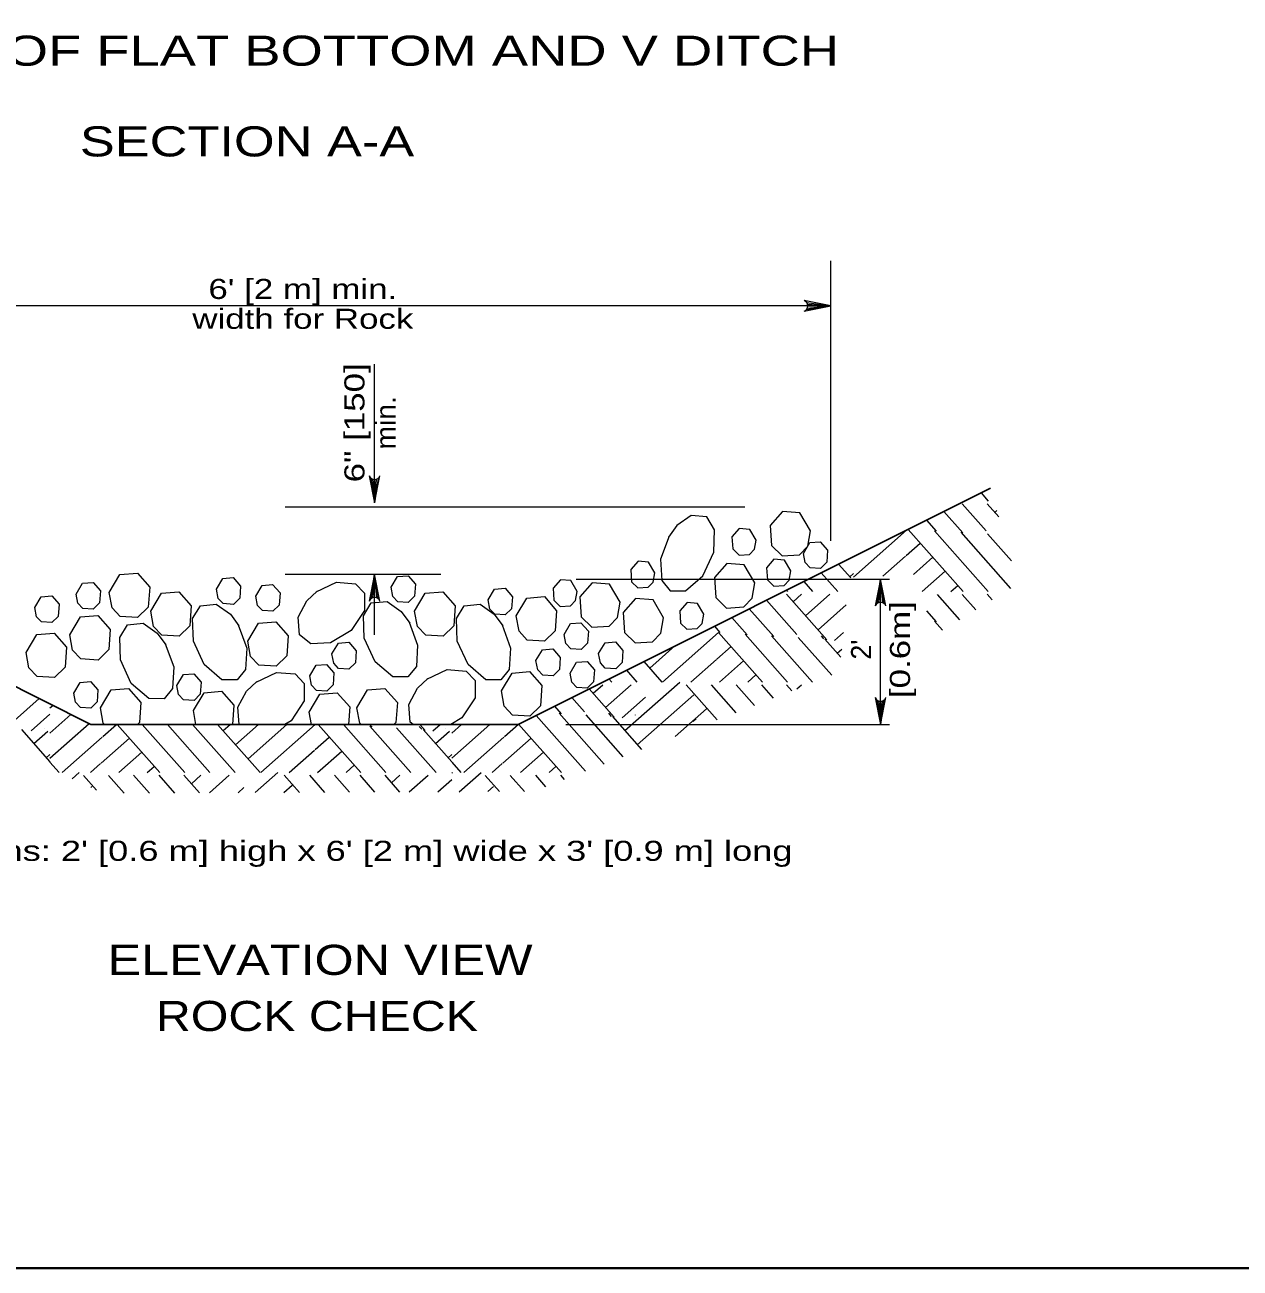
# Model space of a CAD drawing. Extents: x 1083.1 to 1117.1, y 672.5 to 716.5.
# Drawn here: x 1090.8 to 1100.48, y 695.01 to 704.92 of the extents above; entities that cross this region are included whole.
import ezdxf
from ezdxf.enums import TextEntityAlignment as Align

# ---------------------------------------------------------------- set-up
doc = ezdxf.new("R2010")
doc.units = 0
doc.header["$LTSCALE"] = 0.062
doc.layers.add('1', color=7, linetype='Continuous', lineweight=13)

msp = doc.modelspace()

# ---------------------------------------------------------------- linework, layer by layer
at = {"layer": '1'}
for p, q in [((1097.22183, 700.80767), (1097.22183, 703.03942)), ((1097.02833, 702.7075), (1097.22183, 702.68042)), ((1097.22183, 702.68042), (1088.68708, 702.68042)), ((1097.026, 702.6505), (1097.22183, 702.68042)), ((1097.03342, 702.663), (1097.22183, 702.68042)), ((1097.03483, 702.69408), (1097.22183, 702.68042)), ((1097.03683, 702.68042), (1097.22183, 702.68042)), ((1097.04342, 702.68042), (1097.21917, 702.68042)), ((1093.58383, 701.11083), (1093.58383, 702.21525)), ((1093.55392, 701.30667), (1093.58383, 701.11083)), ((1093.56642, 701.29925), (1093.58383, 701.11083)), ((1093.61092, 701.30433), (1093.58383, 701.11083)), ((1093.5975, 701.29783), (1093.58383, 701.11083)), ((1093.58383, 701.29583), (1093.58383, 701.11083)), ((1093.58383, 701.28925), (1093.58383, 701.1135)), ((1098.41883, 701.18875), (1098.47633, 701.12375)), ((1092.8715, 701.07808), (1096.53592, 701.07808)), ((1098.12233, 701.0405), (1098.27333, 700.86983)), ((1098.26875, 701.10192), (1098.45992, 700.8855)), ((1098.46875, 701.102), (1098.56025, 700.9985)), ((1098.52842, 701.03425), (1098.54558, 701.04942)), ((1097.98342, 700.97108), (1098.06125, 700.88292)), ((1097.40125, 700.51742), (1097.82458, 700.89158)), ((1097.83758, 700.89808), (1098.27625, 700.40225)), ((1097.84483, 700.90175), (1097.84633, 700.9)), ((1098.04667, 700.888), (1098.47633, 700.40225)), ((1098.25825, 700.875), (1098.65442, 700.42758)), ((1098.47058, 700.86208), (1098.66142, 700.64633)), ((1097.82217, 700.68933), (1097.93442, 700.78867)), ((1097.63658, 700.52542), (1097.81758, 700.68558)), ((1097.87908, 700.53925), (1098.03408, 700.67633)), ((1092.8715, 700.54083), (1094.1115, 700.54083)), ((1093.55675, 700.34733), (1093.58383, 700.54083)), ((1093.57017, 700.35383), (1093.58383, 700.54083)), ((1093.58383, 700.05758), (1093.58383, 700.54083)), ((1093.58383, 700.35583), (1093.58383, 700.54083)), ((1093.60125, 700.35242), (1093.58383, 700.54083)), ((1093.61375, 700.345), (1093.58383, 700.54083)), ((1093.58383, 700.36242), (1093.58383, 700.53817)), ((1097.14458, 700.55167), (1097.27675, 700.40225)), ((1097.28342, 700.621), (1097.38092, 700.51083)), ((1097.37192, 700.521), (1097.40125, 700.54692)), ((1097.9505, 700.40225), (1098.13342, 700.56408)), ((1095.19067, 700.50125), (1097.6885, 700.50125)), ((1097.00542, 700.482), (1097.076, 700.40225)), ((1097.59025, 700.30775), (1097.61733, 700.50125)), ((1097.60367, 700.31425), (1097.61733, 700.50125)), ((1097.61733, 699.34308), (1097.61733, 700.50125)), ((1097.61733, 700.31625), (1097.61733, 700.50125)), ((1097.63475, 700.31283), (1097.61733, 700.50125)), ((1097.64725, 700.30542), (1097.61733, 700.50125)), ((1097.61733, 700.32283), (1097.61733, 700.49858)), ((1098.17708, 700.40225), (1098.23275, 700.45183)), ((1096.70925, 700.33392), (1096.951, 700.06042)), ((1096.86667, 700.41267), (1096.87583, 700.40225)), ((1096.86775, 700.38108), (1097.18942, 700.01717)), ((1096.92017, 700.3215), (1096.98758, 700.38117)), ((1097.0195, 700.20917), (1097.21408, 700.38133)), ((1098.068, 700.38033), (1098.24733, 700.17767)), ((1098.26875, 700.38042), (1098.37733, 700.2575)), ((1098.46875, 700.38058), (1098.50717, 700.33717)), ((1096.57008, 700.26442), (1096.76558, 700.04342)), ((1097.11883, 700.09692), (1097.34433, 700.29633)), ((1097.98408, 700.24883), (1098.06125, 700.1615)), ((1096.43108, 700.19492), (1096.5535, 700.05658)), ((1098.04667, 700.1665), (1098.11092, 700.09392)), ((1095.87933, 699.68083), (1096.32617, 700.07583)), ((1096.29258, 700.12558), (1096.33742, 700.07492)), ((1096.32617, 700.07583), (1096.67567, 699.68083)), ((1096.53775, 700.06292), (1096.87583, 699.68083)), ((1096.74933, 700.05), (1097.076, 699.68083)), ((1096.96167, 700.037), (1097.2285, 699.73533)), ((1097.14283, 700.04883), (1097.16333, 700.02567)), ((1097.25133, 700.01333), (1097.32175, 700.07567)), ((1095.77742, 699.79083), (1095.97858, 699.96867)), ((1096.31325, 699.86425), (1096.4255, 699.96358)), ((1097.17325, 700.02408), (1097.30175, 699.87883)), ((1097.27258, 699.91175), (1097.30825, 699.94333)), ((1095.73008, 699.84433), (1095.87475, 699.68083)), ((1096.1055, 699.68083), (1096.30867, 699.8605)), ((1096.3325, 699.68083), (1096.52517, 699.85125)), ((1095.59125, 699.775), (1095.67458, 699.68083)), ((1096.55867, 699.68083), (1096.6245, 699.739)), ((1095.32567, 699.59133), (1095.40233, 699.65908)), ((1095.425, 699.47908), (1095.62833, 699.659)), ((1095.45225, 699.7055), (1095.47408, 699.68083)), ((1095.57875, 699.29392), (1096.016, 699.68083)), ((1096.06683, 699.65925), (1096.31492, 699.37892)), ((1096.26658, 699.65933), (1096.46342, 699.43692)), ((1096.467, 699.65942), (1096.61242, 699.495)), ((1096.66767, 699.6595), (1096.76158, 699.55325)), ((1096.86775, 699.65967), (1096.9105, 699.61133)), ((1096.95058, 699.62692), (1096.98758, 699.65967)), ((1090.71333, 699.3755), (1090.91067, 699.55008)), ((1095.15583, 699.55725), (1095.25717, 699.44258)), ((1095.29467, 699.62667), (1095.49442, 699.40067)), ((1095.55883, 699.39667), (1095.74458, 699.561)), ((1095.67808, 699.18167), (1096.12917, 699.58008)), ((1097.58742, 699.53892), (1097.61733, 699.34308)), ((1097.59992, 699.5315), (1097.61733, 699.34308)), ((1097.64442, 699.53658), (1097.61733, 699.34308)), ((1090.99575, 699.4745), (1091.01925, 699.49525)), ((1092.15975, 699.34308), (1092.13892, 699.45367)), ((1093.08075, 699.34308), (1093.06225, 699.44092)), ((1095.01675, 699.48767), (1095.07058, 699.42683)), ((1095.0555, 699.43208), (1095.41383, 699.02742)), ((1095.44783, 699.43225), (1095.4695, 699.40775)), ((1095.97975, 699.24817), (1096.22908, 699.46858)), ((1097.631, 699.53008), (1097.61733, 699.34308)), ((1097.61733, 699.52808), (1097.61733, 699.34308)), ((1097.61733, 699.5215), (1097.61733, 699.34575)), ((1090.84583, 699.29192), (1090.99575, 699.4245)), ((1090.99575, 699.2745), (1091.16325, 699.42258)), ((1090.99575, 699.0745), (1091.30725, 699.34983)), ((1091.41667, 699.24642), (1091.52592, 699.34308)), ((1091.53125, 699.34308), (1091.87075, 698.95933)), ((1091.73142, 699.34308), (1092.07083, 698.95933)), ((1091.93158, 699.34308), (1092.27133, 698.95933)), ((1092.13233, 699.34308), (1092.47183, 698.95933)), ((1092.3325, 699.34308), (1092.672, 698.95933)), ((1092.376, 699.29392), (1092.43158, 699.34308)), ((1092.47533, 699.18167), (1092.65808, 699.34308)), ((1092.57467, 699.06933), (1092.88433, 699.34308)), ((1092.67658, 698.95933), (1093.11058, 699.34308)), ((1093.13342, 699.34308), (1093.47292, 698.95933)), ((1093.335, 699.34142), (1093.67308, 698.95933)), ((1093.34367, 699.34308), (1093.35075, 699.33508)), ((1093.54408, 699.34308), (1093.56283, 699.32192)), ((1093.74467, 699.34308), (1093.74825, 699.339)), ((1093.94483, 699.34308), (1093.98667, 699.29575)), ((1094.04858, 699.29192), (1094.10642, 699.34308)), ((1094.1985, 699.2745), (1094.27608, 699.34308)), ((1094.1985, 699.0745), (1094.50233, 699.34308)), ((1094.61942, 699.24642), (1094.73017, 699.34442)), ((1094.732, 699.34533), (1095.0735, 698.95933)), ((1094.87075, 699.41475), (1095.26483, 698.96925)), ((1095.10808, 699.34308), (1097.6885, 699.34308)), ((1095.26783, 699.41908), (1095.56292, 699.08558)), ((1095.47942, 699.40617), (1095.71175, 699.14358)), ((1095.65992, 699.41908), (1095.66142, 699.41742)), ((1096.12317, 699.36683), (1096.14817, 699.38892)), ((1090.76775, 699.30258), (1090.99575, 699.04483)), ((1090.86708, 699.19033), (1090.97933, 699.28967)), ((1090.94942, 699.31417), (1090.94975, 699.31383)), ((1091.09183, 698.95933), (1091.41208, 699.24267)), ((1093.1105, 699.14275), (1093.22275, 699.24208)), ((1093.54658, 699.3285), (1093.87325, 698.95933)), ((1093.75892, 699.3155), (1094.074, 698.95933)), ((1093.94008, 699.32733), (1093.96058, 699.30417)), ((1093.9705, 699.30258), (1094.1985, 699.04483)), ((1094.06983, 699.19033), (1094.18208, 699.28967)), ((1094.15217, 699.31417), (1094.1525, 699.31383)), ((1094.29458, 698.95933), (1094.61483, 699.24267)), ((1091.40367, 699.03442), (1091.62858, 699.23342)), ((1092.90275, 698.95933), (1093.10592, 699.13908)), ((1094.60642, 699.03442), (1094.83133, 699.23342)), ((1090.96642, 699.078), (1090.99575, 699.104)), ((1090.99575, 699.043), (1091.06975, 698.95933)), ((1091.545, 698.95933), (1091.72792, 699.12117)), ((1093.12975, 698.95933), (1093.32242, 699.12983)), ((1094.16917, 699.078), (1094.1985, 699.104)), ((1094.1985, 699.043), (1094.2725, 698.95933)), ((1094.74775, 698.95933), (1094.93067, 699.12117)), ((1091.17142, 698.90817), (1091.22933, 698.95933)), ((1091.26242, 698.93717), (1091.366, 698.82017)), ((1091.31875, 698.95933), (1091.39908, 699.03042)), ((1091.4625, 698.93733), (1091.5885, 698.79467)), ((1091.6625, 698.93742), (1091.78808, 698.7955)), ((1091.77158, 698.95933), (1091.82725, 699.00892)), ((1091.86325, 698.9375), (1091.98783, 698.79642)), ((1092.06325, 698.93767), (1092.18725, 698.79733)), ((1092.12292, 698.86983), (1092.19958, 698.93767)), ((1092.26758, 698.79767), (1092.42558, 698.9375)), ((1092.63242, 698.79925), (1092.81325, 698.95933)), ((1092.86408, 698.93775), (1092.98525, 698.80083)), ((1093.06383, 698.93792), (1093.18433, 698.80175)), ((1093.26425, 698.938), (1093.384, 698.80267)), ((1093.35592, 698.95933), (1093.42175, 699.01758)), ((1093.46492, 698.93808), (1093.58383, 698.8035)), ((1093.665, 698.93817), (1093.78325, 698.80442)), ((1093.71742, 698.8785), (1093.78483, 698.93817)), ((1093.86025, 698.80475), (1094.01133, 698.93842)), ((1094.1985, 698.9535), (1094.20508, 698.95933)), ((1094.25908, 698.8065), (1094.43208, 698.95933)), ((1094.46517, 698.93717), (1094.5795, 698.80792)), ((1094.5215, 698.95933), (1094.60183, 699.03042)), ((1094.66525, 698.93733), (1094.77875, 698.80883)), ((1094.86525, 698.93742), (1094.94683, 698.84517)), ((1094.97433, 698.95933), (1095.03, 699.00892)), ((1095.066, 698.9375), (1095.09608, 698.90342)), ((1091.32092, 698.8405), (1091.32875, 698.84742)), ((1092.49558, 698.79867), (1092.54183, 698.83958)), ((1092.86042, 698.80033), (1092.92642, 698.85858)), ((1094.08767, 698.80575), (1094.1985, 698.90383)), ((1094.48633, 698.8075), (1094.5315, 698.84742))]:
    msp.add_line(p, q, dxfattribs=at)
at = {"layer": '1', "lineweight": 25}
msp.add_line((1091.32067, 699.34308), (1087.81892, 701.107), dxfattribs=at)
for points in [[(1116.62642, 695.00825), (1085.12642, 695.00825), (1085.12642, 716.00825)], [(1091.32067, 699.34308), (1094.7275, 699.34308), (1098.49467, 701.22667)]]:
    msp.add_lwpolyline(points, dxfattribs=at)
at = {"layer": '1', "lineweight": 40}
msp.add_lwpolyline([(1085.12642, 716.00825), (1116.62642, 716.00825), (1116.62642, 695.00825), (1085.12642, 695.00825)], close=True, dxfattribs=at)
msp.add_lwpolyline([(1085.12642, 716.00825), (1116.62642, 716.00825), (1116.62642, 695.00825), (1085.12642, 695.00825)], close=True, dxfattribs=at)
at = {"layer": '1'}
for points in [[(1097.00808, 702.63767), (1097.22183, 702.68042), (1097.00808, 702.72317)], [(1093.54108, 701.32458), (1093.58383, 701.11083), (1093.62658, 701.32458)], [(1087.793, 701.12375), (1091.32067, 699.34308), (1094.7275, 699.34308), (1098.49467, 701.22667)], [(1095.93133, 700.84508), (1095.86325, 700.66117), (1095.87342, 700.4905), (1095.94, 700.408), (1096.06183, 700.40833), (1096.20192, 700.52858), (1096.28833, 700.71667), (1096.29375, 700.8955), (1096.2325, 700.9975), (1096.10717, 701.0095), (1095.99375, 700.93), (1095.9265, 700.83758)], [(1091.46808, 700.39625), (1091.55333, 700.53875), (1091.6925, 700.55042), (1091.79092, 700.43825), (1091.7795, 700.278), (1091.69458, 700.19525), (1091.55658, 700.20392), (1091.49117, 700.27383), (1091.46808, 700.39592)], [(1093.62658, 700.32708), (1093.58383, 700.54083), (1093.54108, 700.32708)], [(1093.11867, 700.3995), (1093.28042, 700.47633), (1093.431, 700.46467), (1093.50358, 700.38933), (1093.50333, 700.251), (1093.39742, 700.09175), (1093.2315, 699.99333), (1093.07458, 699.987), (1092.98458, 700.05692), (1092.97408, 700.19917), (1093.044, 700.32817), (1093.12533, 700.40467)], [(1097.66008, 700.2875), (1097.61733, 700.50125), (1097.57458, 700.2875)], [(1091.79867, 700.24683), (1091.88392, 700.38933), (1092.02308, 700.401), (1092.1215, 700.28883), (1092.11042, 700.12867), (1092.02517, 700.04583), (1091.8875, 700.0545), (1091.82183, 700.12442), (1091.79867, 700.2465)], [(1093.90283, 700.24683), (1093.988, 700.38933), (1094.12725, 700.401), (1094.22567, 700.28883), (1094.2145, 700.12867), (1094.12933, 700.04583), (1093.99167, 700.0545), (1093.92592, 700.12442), (1093.90283, 700.2465)], [(1092.49617, 700.13642), (1092.564, 699.9525), (1092.55383, 699.78183), (1092.48717, 699.69933), (1092.36567, 699.69967), (1092.22558, 699.81992), (1092.13892, 700.008), (1092.13317, 700.18683), (1092.195, 700.28883), (1092.32008, 700.30083), (1092.43383, 700.22133), (1092.50067, 700.12892)], [(1093.85867, 700.15925), (1093.92675, 699.97533), (1093.91658, 699.80467), (1093.85, 699.72217), (1093.72817, 699.72242), (1093.58808, 699.84275), (1093.50167, 700.03083), (1093.49625, 700.20967), (1093.5575, 700.31167), (1093.68283, 700.32367), (1093.79625, 700.24417), (1093.8635, 700.15175)], [(1094.60033, 700.13642), (1094.66817, 699.9525), (1094.65792, 699.78183), (1094.59133, 699.69933), (1094.46983, 699.69967), (1094.32975, 699.81992), (1094.243, 700.008), (1094.23733, 700.18683), (1094.29917, 700.28883), (1094.42425, 700.30083), (1094.53792, 700.22133), (1094.60483, 700.12892)], [(1091.91383, 699.9855), (1091.98192, 699.80158), (1091.97175, 699.63092), (1091.90517, 699.54842), (1091.78333, 699.54875), (1091.64325, 699.669), (1091.55683, 699.85708), (1091.55142, 700.03592), (1091.61267, 700.13792), (1091.738, 700.14992), (1091.85142, 700.07042), (1091.91867, 699.978)], [(1092.63867, 699.681), (1092.801, 699.7575), (1092.95067, 699.74583), (1093.023, 699.67025), (1093.023, 699.53192), (1092.91742, 699.37292), (1092.86717, 699.34308)], [(1094.00083, 699.70383), (1094.1635, 699.78033), (1094.3135, 699.76867), (1094.38575, 699.693), (1094.3855, 699.55475), (1094.27983, 699.39575), (1094.19142, 699.34308)], [(1091.39758, 699.47642), (1091.48242, 699.61892), (1091.62167, 699.63092), (1091.72033, 699.51875), (1091.70892, 699.3585), (1091.69308, 699.34308)], [(1092.50392, 699.34308), (1092.49383, 699.48067), (1092.56367, 699.60967), (1092.64533, 699.6855)], [(1093.44242, 699.47642), (1093.52733, 699.61892), (1093.6665, 699.63092), (1093.76517, 699.51875), (1093.75383, 699.3585), (1093.73792, 699.34308)], [(1093.89008, 699.34308), (1093.86708, 699.36092), (1093.85658, 699.50342), (1093.9265, 699.63242), (1094.0075, 699.70833)], [(1092.13892, 699.45367), (1092.22383, 699.59617), (1092.363, 699.60817), (1092.462, 699.49592), (1092.45058, 699.34308)], [(1093.06225, 699.44092), (1093.14775, 699.58375), (1093.28667, 699.59542), (1093.38508, 699.48325), (1093.37508, 699.34308)], [(1097.57458, 699.55683), (1097.61733, 699.34308), (1097.66008, 699.55683)], [(1091.43067, 699.34308), (1091.42033, 699.354), (1091.39758, 699.47642)], [(1093.47558, 699.34308), (1093.46517, 699.354), (1093.44242, 699.47642)]]:
    msp.add_lwpolyline(points, dxfattribs=at)
for points in [[(1097.05892, 700.88708), (1096.97433, 701.02992), (1096.83483, 701.04158), (1096.73675, 700.92942), (1096.74808, 700.76983), (1096.833, 700.68642), (1096.97075, 700.69508), (1097.03675, 700.765)], [(1096.62542, 700.81283), (1096.57475, 700.89833), (1096.491, 700.9055), (1096.43192, 700.838), (1096.43883, 700.742), (1096.4895, 700.69225), (1096.57233, 700.69767), (1096.61192, 700.73933)], [(1097.00233, 700.70733), (1097.053, 700.79283), (1097.13675, 700.8), (1097.19583, 700.7325), (1097.18892, 700.6365), (1097.13825, 700.58675), (1097.05542, 700.59217), (1097.01583, 700.63383)], [(1095.81917, 700.55208), (1095.7685, 700.63758), (1095.68475, 700.64475), (1095.62567, 700.57725), (1095.63258, 700.48125), (1095.68325, 700.4315), (1095.76608, 700.43692), (1095.80567, 700.47858)], [(1096.61533, 700.47175), (1096.53075, 700.61458), (1096.39125, 700.62625), (1096.29317, 700.51408), (1096.3045, 700.3545), (1096.38942, 700.27108), (1096.52717, 700.27975), (1096.59317, 700.34967)], [(1096.90158, 700.56725), (1096.85092, 700.65275), (1096.76717, 700.65992), (1096.70808, 700.59242), (1096.715, 700.49642), (1096.76567, 700.44667), (1096.8485, 700.45208), (1096.88808, 700.49375)], [(1093.71608, 700.43658), (1093.76675, 700.52208), (1093.8505, 700.52925), (1093.90958, 700.46175), (1093.90267, 700.36575), (1093.852, 700.316), (1093.76917, 700.32142), (1093.72958, 700.36308)], [(1091.2045, 700.383), (1091.25517, 700.4685), (1091.33892, 700.47567), (1091.398, 700.40817), (1091.39108, 700.31217), (1091.34042, 700.26242), (1091.25758, 700.26783), (1091.218, 700.3095)], [(1092.32242, 700.42125), (1092.37308, 700.50675), (1092.45683, 700.51392), (1092.51592, 700.44642), (1092.509, 700.35042), (1092.45833, 700.30067), (1092.3755, 700.30608), (1092.33592, 700.34775)], [(1092.63658, 700.36617), (1092.68725, 700.45167), (1092.771, 700.45883), (1092.83008, 700.39133), (1092.82317, 700.29533), (1092.7725, 700.24558), (1092.68967, 700.251), (1092.65008, 700.29267)], [(1094.4895, 700.33633), (1094.54017, 700.42183), (1094.62392, 700.429), (1094.683, 700.3615), (1094.67608, 700.2655), (1094.62542, 700.21575), (1094.54258, 700.22117), (1094.503, 700.26283)], [(1095.19992, 700.404), (1095.14925, 700.4895), (1095.0655, 700.49667), (1095.00642, 700.42917), (1095.01333, 700.33317), (1095.064, 700.28342), (1095.14683, 700.28883), (1095.18642, 700.3305)], [(1095.54117, 700.31825), (1095.45658, 700.46108), (1095.31708, 700.47275), (1095.219, 700.36058), (1095.23033, 700.201), (1095.31525, 700.11758), (1095.453, 700.12625), (1095.519, 700.19617)], [(1090.87525, 700.27575), (1090.92592, 700.36125), (1091.00967, 700.36842), (1091.06875, 700.30092), (1091.06183, 700.20492), (1091.01117, 700.15517), (1090.92833, 700.16058), (1090.88875, 700.20225)], [(1094.713, 700.20775), (1094.79758, 700.35058), (1094.93708, 700.36225), (1095.03517, 700.25008), (1095.02383, 700.0905), (1094.93892, 700.00708), (1094.80117, 700.01575), (1094.73517, 700.08567)], [(1095.88817, 700.194), (1095.80358, 700.33683), (1095.66408, 700.3485), (1095.566, 700.23633), (1095.57733, 700.07675), (1095.66225, 699.99333), (1095.8, 700.002), (1095.866, 700.07192)], [(1096.20975, 700.22267), (1096.15908, 700.30817), (1096.07533, 700.31533), (1096.01625, 700.24783), (1096.02317, 700.15183), (1096.07383, 700.10208), (1096.15667, 700.1075), (1096.19625, 700.14917)], [(1091.15325, 700.05725), (1091.23783, 700.20008), (1091.37733, 700.21175), (1091.47542, 700.09958), (1091.46408, 699.94), (1091.37917, 699.85658), (1091.24142, 699.86525), (1091.17542, 699.93517)], [(1092.573, 700.00742), (1092.65758, 700.15025), (1092.79708, 700.16192), (1092.89517, 700.04975), (1092.88383, 699.89017), (1092.79892, 699.80675), (1092.66117, 699.81542), (1092.59517, 699.88533)], [(1095.09442, 700.06125), (1095.14508, 700.14675), (1095.22883, 700.15392), (1095.28792, 700.08642), (1095.281, 699.99042), (1095.23033, 699.94067), (1095.1475, 699.94608), (1095.10792, 699.98775)], [(1090.80625, 699.91767), (1090.89083, 700.0605), (1091.03033, 700.07217), (1091.12842, 699.96), (1091.11708, 699.80042), (1091.03217, 699.717), (1090.89442, 699.72567), (1090.82842, 699.79558)], [(1093.2435, 699.90517), (1093.29483, 699.99092), (1093.37817, 699.99783), (1093.43758, 699.93067), (1093.43067, 699.83467), (1093.37942, 699.7845), (1093.29717, 699.78992), (1093.25758, 699.83167)], [(1094.87042, 699.85225), (1094.92175, 699.938), (1095.00508, 699.94492), (1095.0645, 699.87775), (1095.05758, 699.78175), (1095.00633, 699.73158), (1094.92408, 699.737), (1094.8845, 699.77875)], [(1095.37008, 699.908), (1095.42075, 699.9935), (1095.5045, 700.00067), (1095.56358, 699.93317), (1095.55667, 699.83717), (1095.506, 699.78742), (1095.42317, 699.79283), (1095.38358, 699.8345)], [(1095.14283, 699.75317), (1095.19417, 699.83892), (1095.2775, 699.84583), (1095.33692, 699.77867), (1095.33, 699.68267), (1095.27875, 699.6325), (1095.1965, 699.63792), (1095.15692, 699.67967)], [(1092.00783, 699.65492), (1092.05908, 699.74042), (1092.1425, 699.74767), (1092.20133, 699.68017), (1092.19442, 699.58417), (1092.144, 699.53433), (1092.06117, 699.53942), (1092.02158, 699.58142)], [(1093.0665, 699.72967), (1093.11783, 699.81517), (1093.20117, 699.82233), (1093.26, 699.75483), (1093.25308, 699.65883), (1093.20242, 699.609), (1093.11958, 699.61417), (1093.08, 699.65617)], [(1094.59492, 699.61), (1094.6795, 699.75283), (1094.819, 699.7645), (1094.91708, 699.65233), (1094.90575, 699.49275), (1094.82083, 699.40933), (1094.68308, 699.418), (1094.61708, 699.48792)], [(1091.18467, 699.59333), (1091.236, 699.67883), (1091.31933, 699.686), (1091.37817, 699.6185), (1091.37125, 699.5225), (1091.32058, 699.47267), (1091.23775, 699.47783), (1091.19817, 699.51983)]]:
    msp.add_lwpolyline(points, close=True, dxfattribs=at)
for centre, start, end in [((1096.99084, 702.68045), 292.08605, 67.91218), ((1093.58385, 701.34184), 202.08605, 337.91218), ((1093.58376, 700.30983), 22.08605, 157.91218), ((1097.61729, 700.27024), 22.08605, 157.91218), ((1097.61738, 699.57409), 202.08605, 337.91218)]:
    msp.add_arc(centre, 0.04613, start, end, dxfattribs=at)

# ---------------------------------------------------------------- texts
for s, height, width, p in [('SIDE VIEW OF FLAT BOTTOM AND V DITCH', 0.24, 1.35, (1088.28408, 704.59517)), ('SECTION A-A', 0.24, 1.3, (1091.23375, 703.87192)), ("Minimum dimensions: 2' [0.6 m] high x 6' [2 m] wide x 3' [0.9 m] long", 0.16, 1.35, (1088.20975, 698.25542)), ('ELEVATION VIEW', 0.24, 1.25, (1091.45475, 697.34633))]:
    msp.add_text(s, height=height, dxfattribs=dict(at, width=width)).set_placement(p)
for s, height, width, p in [("6' [2 m] min.", 0.16, 1.3, (1093.01158, 702.73533)), ('width for Rock', 0.16, 1.3, (1093.01158, 702.49733)), ('ROCK CHECK', 0.24, 1.2, (1093.124, 696.89875))]:
    msp.add_text(s, height=height, dxfattribs=dict(at, width=width)).set_placement(p, align=Align.CENTER)
for s, width, p in [('6" [150]', 1.3, (1093.50292, 701.74783)), ('min.', 1.05, (1093.75292, 701.74783)), ('[0.6m]', 1.3, (1097.85233, 699.93971))]:
    msp.add_text(s, height=0.16, rotation=90, dxfattribs=dict(at, width=width)).set_placement(p, align=Align.CENTER)
msp.add_text("2'", height=0.16, rotation=90, dxfattribs=at).set_placement((1097.54233, 699.93971), align=Align.CENTER)

doc.saveas('drawing.dxf')
